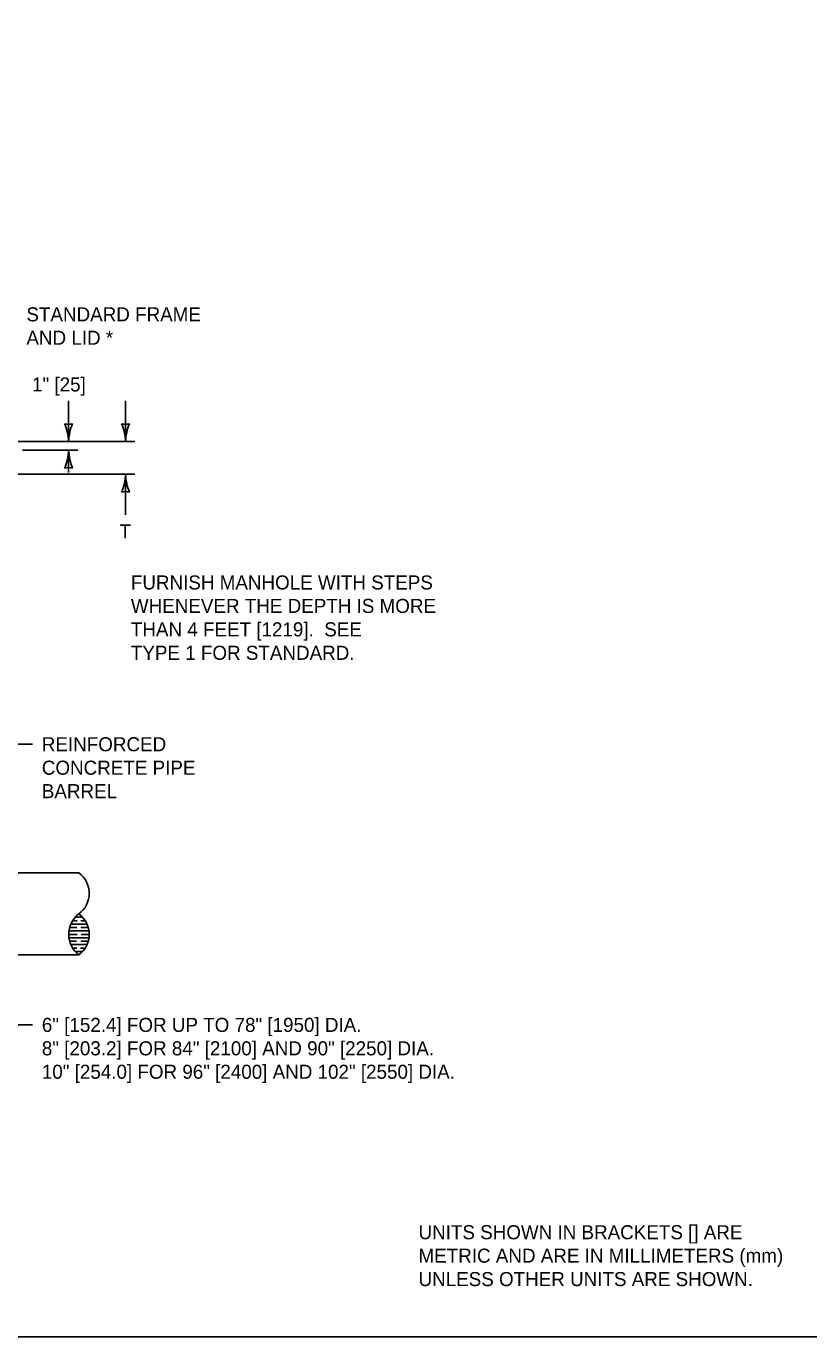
# Model space of a CAD drawing. Extents: x 49991.4 to 50028.3, y 49987.6 to 50011.4.
# Drawn here: x 50008.72 to 50012.06, y 49987.8 to 49993.39 of the extents above; entities that cross this region are included whole.
import ezdxf

# ---------------------------------------------------------------- set-up
doc = ezdxf.new("R2010")
doc.units = 0
for name, color, linetype in [('Level 1', 7, 'Continuous'), ('Level 2', 7, 'Continuous'), ('Level 3', 7, 'Continuous')]:
    doc.layers.add(name, color=color, linetype=linetype)

msp = doc.modelspace()

# ---------------------------------------------------------------- linework, layer by layer
at = {"layer": 'Level 1'}
for p, q in [((50008.3376, 49989.7777), (50008.9435, 49989.7777)), ((50008.9594, 49989.5882), (50008.9276, 49989.5882)), ((50008.9341, 49989.5444), (50008.9037, 49989.5444)), ((50008.9781, 49989.559), (50008.9089, 49989.559)), ((50008.9364, 49989.5736), (50008.9166, 49989.5736)), ((50008.9833, 49989.5444), (50008.9513, 49989.5444)), ((50008.9704, 49989.5736), (50008.9521, 49989.5736)), ((50008.9357, 49989.5152), (50008.8997, 49989.5152)), ((50008.9863, 49989.5298), (50008.9007, 49989.5298)), ((50008.9863, 49989.5007), (50008.9007, 49989.5007)), ((50008.9334, 49989.4861), (50008.9037, 49989.4861)), ((50008.9833, 49989.4861), (50008.9521, 49989.4861)), ((50008.9872, 49989.5152), (50008.9529, 49989.5152)), ((50008.3376, 49989.4277), (50008.9435, 49989.4277)), ((50008.9781, 49989.4715), (50008.9089, 49989.4715)), ((50008.935, 49989.4569), (50008.9166, 49989.4569)), ((50008.9594, 49989.4423), (50008.9276, 49989.4423)), ((50008.9704, 49989.4569), (50008.9506, 49989.4569))]:
    msp.add_line(p, q, dxfattribs=at)
msp.add_lwpolyline([(49999.3835, 49998.9992), (50016.7501, 49998.9992), (50016.7501, 49987.7988), (49999.3835, 49987.7988)], close=True, dxfattribs=at)
for centre, start, end in [((50008.8779, 49989.6902), 306.8699, 53.1301), ((50009.0091, 49989.5152), 126.8699, 233.1301), ((50008.8779, 49989.5152), 306.8699, 53.1301)]:
    msp.add_arc(centre, 0.1094, start, end, dxfattribs=at)
at = {"layer": 'Level 3'}
for p, q in [((50008.8994, 49991.7911), (50008.8994, 49991.6177)), ((50009.1424, 49991.7911), (50009.1424, 49991.6177)), ((50008.5026, 49991.6177), (50009.1824, 49991.6177)), ((50008.7024, 49991.5801), (50008.9394, 49991.5801)), ((50008.8994, 49991.5801), (50008.8994, 49991.4856)), ((50008.5026, 49991.4777), (50009.1824, 49991.4777)), ((50009.1424, 49991.4777), (50009.1424, 49991.3043)), ((50008.7452, 49990.3263), (50008.654, 49990.3263)), ((50008.7452, 49989.1293), (50008.6776, 49989.1293))]:
    msp.add_line(p, q, dxfattribs=at)
for centre, radius, start, end in [((50008.8994, 49991.7459), 0.0548, 252.1388, 287.8612), ((50008.6667, 49991.6062), 0.233, 2.8273, 22.0772), ((50009.1215, 49991.6086), 0.2223, 157.456, 177.6395), ((50009.1424, 49991.7459), 0.0548, 252.1388, 287.8612), ((50008.9097, 49991.6062), 0.233, 2.8273, 22.0772), ((50009.3645, 49991.6086), 0.2223, 157.456, 177.6395), ((50008.6773, 49991.5893), 0.2223, 337.456, 357.6395), ((50009.1321, 49991.5916), 0.233, 182.8273, 202.0772), ((50008.8994, 49991.4519), 0.0548, 72.1388, 107.8612), ((50008.9203, 49991.4869), 0.2223, 337.456, 357.6395), ((50009.3751, 49991.4892), 0.233, 182.8273, 202.0772), ((50009.1424, 49991.3495), 0.0548, 72.1388, 107.8612)]:
    msp.add_arc(centre, radius, start, end, dxfattribs=at)

# ---------------------------------------------------------------- texts
at = {"layer": 'Level 2'}
for s, p in [('STANDARD FRAME', (50008.7194, 49992.1302)), ('AND LID *', (50008.7194, 49992.0302)), ('1" [25]', (50008.7436, 49991.8311)), ('T', (50009.1164, 49991.2043)), ('FURNISH MANHOLE WITH STEPS', (50009.1651, 49990.9864)), ('WHENEVER THE DEPTH IS MORE', (50009.1651, 49990.8864)), ('THAN 4 FEET [1219].  SEE', (50009.1651, 49990.7864)), ('TYPE 1 FOR STANDARD.', (50009.1651, 49990.6864)), ('REINFORCED', (50008.7852, 49990.2963)), ('CONCRETE PIPE', (50008.7852, 49990.1963)), ('BARREL', (50008.7852, 49990.0963)), ('6" [152.4] FOR UP TO 78" [1950] DIA.', (50008.7852, 49989.0993)), ('8" [203.2] FOR 84" [2100] AND 90" [2250] DIA.', (50008.7852, 49988.9993)), ('10" [254.0] FOR 96" [2400] AND 102" [2550] DIA.', (50008.7852, 49988.8993)), ('UNITS SHOWN IN BRACKETS [] ARE ', (50010.3921, 49988.2149)), ('METRIC AND ARE IN MILLIMETERS (mm) ', (50010.3921, 49988.1149)), ('UNLESS OTHER UNITS ARE SHOWN.', (50010.3921, 49988.0149))]:
    msp.add_text(s, height=0.06, dxfattribs=at).set_placement(p)

doc.saveas('drawing.dxf')
